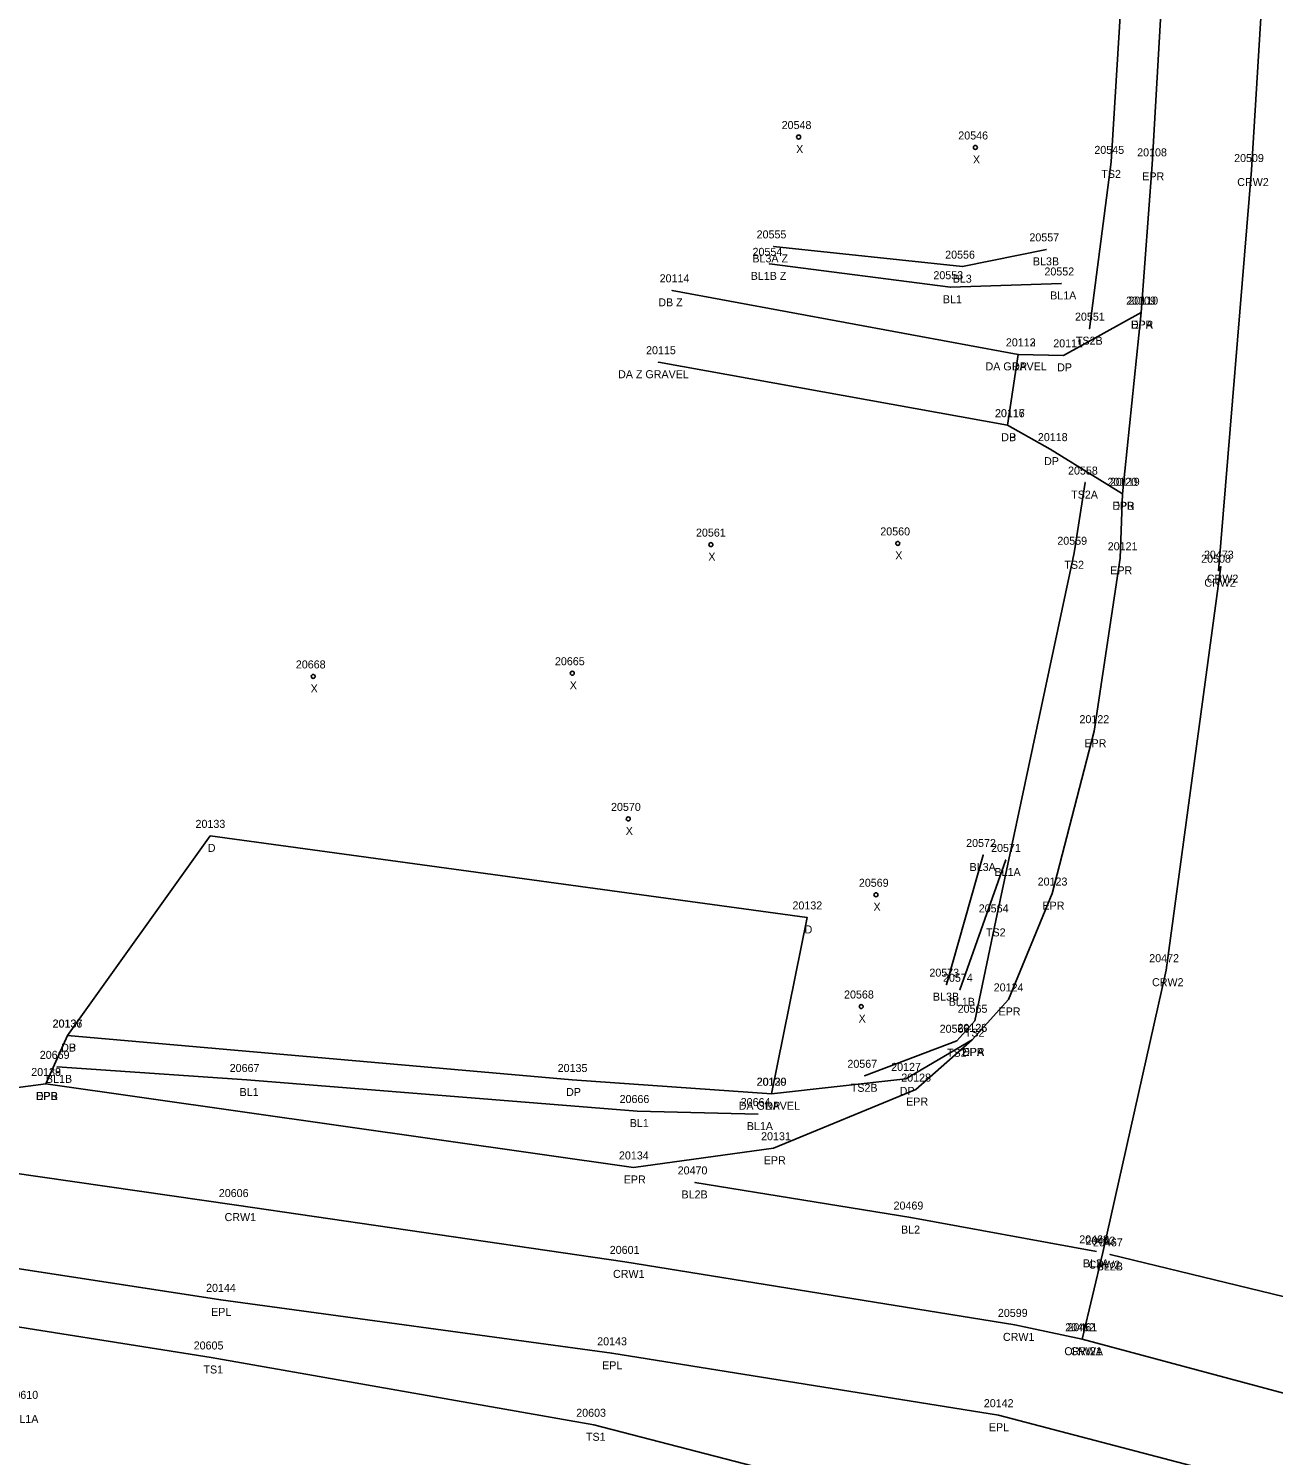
# Model space of a CAD drawing. Extents: x 1813127 to 1818290, y 1178171 to 1179900.
# Drawn here: x 1813520.5 to 1813676.1, y 1178739.3 to 1178917.6 of the extents above; entities that cross this region are included whole.
import ezdxf

# ---------------------------------------------------------------- set-up
doc = ezdxf.new("R2010")
doc.units = 0
for name, color, linetype in [('RD_DTM_BkLn1', 7, 'Continuous'), ('RD_DTM_BkLn2', 7, 'Continuous'), ('RD_EX_Driveway', 7, 'Continuous'), ('RD_EX_Driveway_txCode', 7, 'Continuous'), ('RD_EX_Road', 7, 'Continuous'), ('RD_EX_Road_txCode', 7, 'Continuous'), ('RD_SMD_Locator', 7, 'Continuous'), ('RD_SMD_Misc', 7, 'Continuous')]:
    doc.layers.add(name, color=color, linetype=linetype)

msp = doc.modelspace()

# ---------------------------------------------------------------- linework, layer by layer
at = {"layer": 'RD_DTM_BkLn1'}
for p, q in [((1813639.78, 1178814.35), (1813635.19, 1178798.15)), ((1813642.61, 1178813.73), (1813636.89, 1178797.51))]:
    msp.add_line(p, q, dxfattribs=at)
for points in [[(1813652.18, 1178753.85), (1813654.73, 1178764.67), (1813662.67, 1178799.96), (1813669.51, 1178850.38), (1813669.19, 1178849.87), (1813673.32, 1178899.93), (1813676.21, 1178946.85), (1813678.62, 1178996.65), (1813680.77, 1179045.99)], [(1813613.59, 1178890.39), (1813637.19, 1178887.86), (1813647.69, 1178890.02)], [(1813649.57, 1178885.76), (1813635.69, 1178885.29), (1813613.07, 1178888.21)], [(1813740.76, 1178717.86), (1813693.97, 1178742.65), (1813652.18, 1178753.85), (1813643.74, 1178755.64), (1813595, 1178763.51), (1813546.44, 1178770.61), (1813497.6, 1178777.62), (1813448.59, 1178785.89), (1813401.09, 1178795.04), (1813353.48, 1178806.76), (1813306.05, 1178819.85), (1813260.03, 1178834.12), (1813213.64, 1178849.47), (1813166.61, 1178866.29)], [(1813611.65, 1178781.98), (1813596.53, 1178782.36), (1813547.76, 1178786.24), (1813524.02, 1178787.88)], [(1813653.94, 1178764.83), (1813630.73, 1178769.05), (1813603.76, 1178773.44)], [(1813708.13, 1178748.38), (1813678.84, 1178758.82), (1813655.66, 1178764.45)]]:
    msp.add_lwpolyline(points, dxfattribs=at)
at = {"layer": 'RD_DTM_BkLn2'}
for points in [[(1813665.28, 1179045.88), (1813659.72, 1178996.23), (1813658.69, 1178948.21), (1813655.81, 1178900.95), (1813653.1, 1178880.11)], [(1813652.52, 1178860.88), (1813651.18, 1178852.11), (1813641.38, 1178806.18), (1813638.75, 1178793.64), (1813636.51, 1178791.14), (1813624.96, 1178786.76)], [(1813728.98, 1178703.48), (1813680.74, 1178720.54), (1813670.9, 1178725.8), (1813665.35, 1178733.78), (1813654.36, 1178734.63), (1813647.32, 1178729.73), (1813639.1, 1178730.74), (1813591.11, 1178743.16), (1813543.28, 1178751.57), (1813511.7, 1178756.57), (1813494.92, 1178760.32), (1813445.74, 1178769.42), (1813422.91, 1178772.94), (1813422.78, 1178770.34)]]:
    msp.add_lwpolyline(points, dxfattribs=at)
at = {"layer": 'RD_EX_Driveway'}
for p, q in [((1813644.18, 1178876.9), (1813600.91, 1178884.9)), ((1813599.2, 1178875.92), (1813642.83, 1178868.05))]:
    msp.add_line(p, q, dxfattribs=at)
for points in [[(1813659.53, 1178882.12), (1813649.82, 1178876.78), (1813644.18, 1178876.9), (1813642.83, 1178868.05), (1813648.18, 1178865.06), (1813657.19, 1178859.48)], [(1813613.34, 1178784.52), (1813617.78, 1178806.55), (1813543.17, 1178816.74), (1813525.31, 1178791.79)], [(1813638.42, 1178791.25), (1813630.13, 1178786.38), (1813613.34, 1178784.52), (1813588.43, 1178786.24), (1813525.31, 1178791.79), (1813522.62, 1178785.74)]]:
    msp.add_lwpolyline(points, dxfattribs=at)
at = {"layer": 'RD_EX_Road'}
for points in [[(1813668.47, 1179045.78), (1813666.19, 1178996.77), (1813663.63, 1178947.81), (1813660.91, 1178900.64), (1813659.53, 1178882.12), (1813657.19, 1178859.48), (1813656.91, 1178851.42), (1813653.67, 1178829.82), (1813648.43, 1178809.53), (1813642.94, 1178796.31), (1813638.42, 1178791.25), (1813631.39, 1178785.04), (1813613.59, 1178777.71), (1813596.09, 1178775.31), (1813522.62, 1178785.74), (1813518.21, 1178785.19)], [(1813732.94, 1178707.95), (1813689.88, 1178731.75), (1813641.71, 1178744.36), (1813593.37, 1178752.09), (1813544.49, 1178758.77), (1813495.45, 1178766.29), (1813446.8, 1178774.66), (1813426.54, 1178777.95), (1813403.21, 1178782.55), (1813398.65, 1178783.84), (1813350.68, 1178796.09), (1813343.23, 1178797.92), (1813318.7, 1178804.23), (1813303.26, 1178808.85), (1813256.8, 1178823.17), (1813209.81, 1178838.91), (1813163.27, 1178855.57)]]:
    msp.add_lwpolyline(points, dxfattribs=at)
at = {"layer": 'RD_SMD_Locator'}
for centre, radius in [((1813616.72, 1178904.05), 0.25), ((1813638.82, 1178902.75), 0.25), ((1813655.81, 1178900.95), 0.001), ((1813660.91, 1178900.64), 0.001), ((1813673.32, 1178899.93), 0.001), ((1813613.59, 1178890.39), 0.001), ((1813647.69, 1178890.02), 0.001), ((1813613.07, 1178888.21), 0.001), ((1813637.19, 1178887.86), 0.001), ((1813600.91, 1178884.9), 0.001), ((1813635.69, 1178885.29), 0.001), ((1813649.57, 1178885.76), 0.001), ((1813659.53, 1178882.12), 0.001), ((1813659.53, 1178882.12), 0.001), ((1813653.1, 1178880.11), 0.001), ((1813599.2, 1178875.92), 0.001), ((1813644.18, 1178876.9), 0.001), ((1813644.18, 1178876.9), 0.001), ((1813649.82, 1178876.78), 0.001), ((1813642.83, 1178868.05), 0.001), ((1813642.83, 1178868.05), 0.001), ((1813648.18, 1178865.06), 0.001), ((1813652.52, 1178860.88), 0.001), ((1813657.19, 1178859.48), 0.001), ((1813657.19, 1178859.48), 0.001), ((1813605.75, 1178853.13), 0.25), ((1813629.12, 1178853.28), 0.25), ((1813651.18, 1178852.11), 0.001), ((1813656.91, 1178851.42), 0.001), ((1813669.19, 1178849.87), 0.001), ((1813669.51, 1178850.38), 0.001), ((1813556.04, 1178836.66), 0.25), ((1813588.43, 1178837.06), 0.25), ((1813653.67, 1178829.82), 0.001), ((1813595.43, 1178818.86), 0.25), ((1813543.17, 1178816.74), 0.001), ((1813639.78, 1178814.35), 0.001), ((1813642.61, 1178813.73), 0.001), ((1813626.39, 1178809.38), 0.25), ((1813648.43, 1178809.53), 0.001), ((1813617.78, 1178806.55), 0.001), ((1813641.38, 1178806.18), 0.001), ((1813662.67, 1178799.96), 0.001), ((1813635.19, 1178798.15), 0.001), ((1813636.89, 1178797.51), 0.001), ((1813624.54, 1178795.42), 0.25), ((1813642.94, 1178796.31), 0.001), ((1813638.75, 1178793.64), 0.001), ((1813525.31, 1178791.79), 0.001), ((1813525.31, 1178791.79), 0.001), ((1813636.51, 1178791.14), 0.001), ((1813638.42, 1178791.25), 0.001), ((1813638.42, 1178791.25), 0.001), ((1813524.02, 1178787.88), 0.001), ((1813624.96, 1178786.76), 0.001), ((1813522.62, 1178785.74), 0.001), ((1813522.62, 1178785.74), 0.001), ((1813547.76, 1178786.24), 0.001), ((1813588.43, 1178786.24), 0.001), ((1813630.13, 1178786.38), 0.001), ((1813631.39, 1178785.04), 0.001), ((1813613.34, 1178784.52), 0.001), ((1813613.34, 1178784.52), 0.001), ((1813596.53, 1178782.36), 0.001), ((1813611.65, 1178781.98), 0.001), ((1813613.59, 1178777.71), 0.001), ((1813596.09, 1178775.31), 0.001), ((1813603.76, 1178773.44), 0.001), ((1813546.44, 1178770.61), 0.001), ((1813630.73, 1178769.05), 0.001), ((1813595, 1178763.51), 0.001), ((1813653.94, 1178764.83), 0.001), ((1813654.73, 1178764.67), 0.001), ((1813655.66, 1178764.45), 0.001), ((1813544.49, 1178758.77), 0.001), ((1813643.74, 1178755.64), 0.001), ((1813652.18, 1178753.85), 0.001), ((1813652.18, 1178753.85), 0.001), ((1813543.28, 1178751.57), 0.001), ((1813593.37, 1178752.09), 0.001), ((1813641.71, 1178744.36), 0.001), ((1813591.11, 1178743.16), 0.001)]:
    msp.add_circle(centre, radius, dxfattribs=at)

# ---------------------------------------------------------------- texts
at = {"layer": 'RD_EX_Driveway_txCode'}
for s, p in [('20114', (1813599.35, 1178885.9)), ('DB Z', (1813599.18, 1178882.9)), ('20110', (1813657.94, 1178883.12)), ('DPA', (1813658.26, 1178880.12)), ('20115', (1813597.65, 1178876.92)), ('20112', (1813642.63, 1178877.9)), ('20113', (1813642.63, 1178877.9)), ('20111', (1813648.55, 1178877.78)), ('DA GRAVEL', (1813640.08, 1178874.9)), ('DP', (1813643.4, 1178874.9)), ('DP', (1813649.04, 1178874.78)), ('DA Z GRAVEL', (1813594.15, 1178873.92)), ('20116', (1813641.26, 1178869.05)), ('20117', (1813641.28, 1178869.05)), ('DB', (1813642.05, 1178866.05)), ('DP', (1813642.05, 1178866.05)), ('20118', (1813646.63, 1178866.06)), ('DP', (1813647.4, 1178863.06)), ('20119', (1813655.64, 1178860.48)), ('DPB', (1813655.94, 1178857.48)), ('20133', (1813541.33, 1178817.74)), ('D', (1813542.86, 1178814.74)), ('20132', (1813615.95, 1178807.55)), ('D', (1813617.47, 1178804.55)), ('20136', (1813523.45, 1178792.79)), ('20137', (1813523.48, 1178792.79)), ('20126', (1813636.57, 1178792.25)), ('DP', (1813524.53, 1178789.79)), ('DB', (1813524.53, 1178789.79)), ('DPA', (1813637.16, 1178789.25)), ('20127', (1813628.29, 1178787.38)), ('20138', (1813520.79, 1178786.74)), ('20135', (1813586.6, 1178787.24)), ('DP', (1813587.65, 1178784.24)), ('20130', (1813611.46, 1178785.52)), ('20129', (1813611.5, 1178785.52)), ('DP', (1813629.35, 1178784.38)), ('DPB', (1813521.37, 1178783.74)), ('DA GRAVEL', (1813609.23, 1178782.52)), ('DP', (1813612.56, 1178782.52))]:
    msp.add_text(s, height=1, dxfattribs=at).set_placement(p)
at = {"layer": 'RD_EX_Road_txCode'}
for s, p in [('20108', (1813659.04, 1178901.64)), ('EPR', (1813659.68, 1178898.64)), ('20109', (1813657.66, 1178883.12)), ('EPR', (1813658.3, 1178880.12)), ('20120', (1813655.32, 1178860.48)), ('EPR', (1813655.96, 1178857.48)), ('20121', (1813655.36, 1178852.42)), ('EPR', (1813655.68, 1178849.42)), ('20122', (1813651.83, 1178830.82)), ('EPR', (1813652.44, 1178827.82)), ('20123', (1813646.6, 1178810.53)), ('EPR', (1813647.2, 1178807.53)), ('20124', (1813641.11, 1178797.31)), ('EPR', (1813641.71, 1178794.31)), ('20125', (1813636.59, 1178792.25)), ('EPR', (1813637.2, 1178789.25)), ('20139', (1813520.79, 1178786.74)), ('20128', (1813629.55, 1178786.04)), ('EPR', (1813521.39, 1178783.74)), ('EPR', (1813630.16, 1178783.04)), ('20131', (1813612.03, 1178778.71)), ('20134', (1813594.26, 1178776.31)), ('EPR', (1813612.36, 1178775.71)), ('EPR', (1813594.86, 1178773.31)), ('20144', (1813542.65, 1178759.77)), ('EPL', (1813543.28, 1178756.77)), ('20143', (1813591.54, 1178753.09)), ('EPL', (1813592.16, 1178750.09)), ('20142', (1813639.87, 1178745.36)), ('EPL', (1813640.5, 1178742.36))]:
    msp.add_text(s, height=1, dxfattribs=at).set_placement(p)
at = {"layer": 'RD_SMD_Misc'}
for s, p in [('20548', (1813614.6, 1178905.05)), ('20546', (1813636.68, 1178903.75)), ('X', (1813616.41, 1178902.05)), ('20545', (1813653.69, 1178901.95)), ('X', (1813638.51, 1178900.75)), ('20509', (1813671.16, 1178900.93)), ('TS2', (1813654.56, 1178898.95)), ('CRW2', (1813671.55, 1178897.93)), ('20555', (1813611.47, 1178891.39)), ('20557', (1813645.57, 1178891.02)), ('20554', (1813610.96, 1178889.21)), ('BL3A Z', (1813610.94, 1178888.39)), ('20556', (1813635.04, 1178888.86)), ('BL3B', (1813646.01, 1178888.02)), ('BL1B Z', (1813610.73, 1178886.21)), ('20553', (1813633.57, 1178886.29)), ('BL3', (1813635.98, 1178885.86)), ('20552', (1813647.45, 1178886.76)), ('BL1A', (1813648.16, 1178883.76)), ('BL1', (1813634.76, 1178883.29)), ('20551', (1813651.27, 1178881.11)), ('TS2B', (1813651.38, 1178878.11)), ('20558', (1813650.4, 1178861.88)), ('TS2A', (1813650.79, 1178858.88)), ('20561', (1813603.89, 1178854.13)), ('20560', (1813626.93, 1178854.28)), ('20559', (1813649.06, 1178853.11)), ('X', (1813605.43, 1178851.13)), ('X', (1813628.8, 1178851.28)), ('TS2', (1813649.94, 1178850.11)), ('20508', (1813667.04, 1178850.87)), ('20473', (1813667.39, 1178851.38)), ('CRW2', (1813667.75, 1178848.38)), ('CRW2', (1813667.43, 1178847.87)), ('20668', (1813553.87, 1178837.66)), ('20665', (1813586.26, 1178838.06)), ('X', (1813555.72, 1178834.66)), ('X', (1813588.11, 1178835.06)), ('20570', (1813593.27, 1178819.86)), ('X', (1813595.11, 1178816.86)), ('20572', (1813637.66, 1178815.35)), ('20571', (1813640.78, 1178814.73)), ('BL3A', (1813638.09, 1178812.35)), ('BL1A', (1813641.2, 1178811.73)), ('20569', (1813624.25, 1178810.38)), ('X', (1813626.08, 1178807.38)), ('20564', (1813639.24, 1178807.18)), ('TS2', (1813640.14, 1178804.18)), ('20472', (1813660.55, 1178800.96)), ('20573', (1813633.07, 1178799.15)), ('20574', (1813634.77, 1178798.51)), ('20568', (1813622.4, 1178796.42)), ('CRW2', (1813660.9, 1178797.96)), ('BL3B', (1813633.51, 1178796.15)), ('BL1B', (1813635.49, 1178795.51)), ('20565', (1813636.6, 1178794.64)), ('X', (1813624.22, 1178793.42)), ('20566', (1813634.35, 1178792.14)), ('TS2', (1813637.5, 1178791.64)), ('20669', (1813521.86, 1178788.88)), ('20567', (1813622.82, 1178787.76)), ('TS2', (1813635.27, 1178789.14)), ('BL1B', (1813522.63, 1178785.88)), ('20667', (1813545.6, 1178787.24)), ('BL1', (1813546.84, 1178784.24)), ('TS2B', (1813623.24, 1178784.76)), ('20666', (1813594.34, 1178783.36)), ('20664', (1813609.48, 1178782.98)), ('BL1', (1813595.61, 1178780.36)), ('BL1A', (1813610.24, 1178779.98)), ('20470', (1813601.6, 1178774.44)), ('20606', (1813544.24, 1178771.61)), ('BL2B', (1813602.08, 1178771.44)), ('20469', (1813628.59, 1178770.05)), ('CRW1', (1813544.96, 1178768.61)), ('BL2', (1813629.52, 1178767.05)), ('20601', (1813593.11, 1178764.51)), ('20468', (1813651.8, 1178765.83)), ('20463', (1813652.59, 1178765.67)), ('20467', (1813653.52, 1178765.45)), ('BL2A', (1813652.25, 1178762.83)), ('CRW2', (1813652.97, 1178762.67)), ('BL2B', (1813653.99, 1178762.45)), ('CRW1', (1813593.52, 1178761.51)), ('20599', (1813641.63, 1178756.64)), ('CRW1', (1813642.26, 1178753.64)), ('20462', (1813650.04, 1178754.85)), ('20461', (1813650.32, 1178754.85)), ('20605', (1813541.1, 1178752.57)), ('CRW2A', (1813649.93, 1178751.85)), ('CRW1', (1813650.7, 1178751.85)), ('TS1', (1813542.32, 1178749.57)), ('20610', (1813517.94, 1178746.4)), ('BL1A', (1813518.42, 1178743.4)), ('20603', (1813588.92, 1178744.16)), ('TS1', (1813590.14, 1178741.16))]:
    msp.add_text(s, height=1, dxfattribs=at).set_placement(p)

doc.saveas('drawing.dxf')
